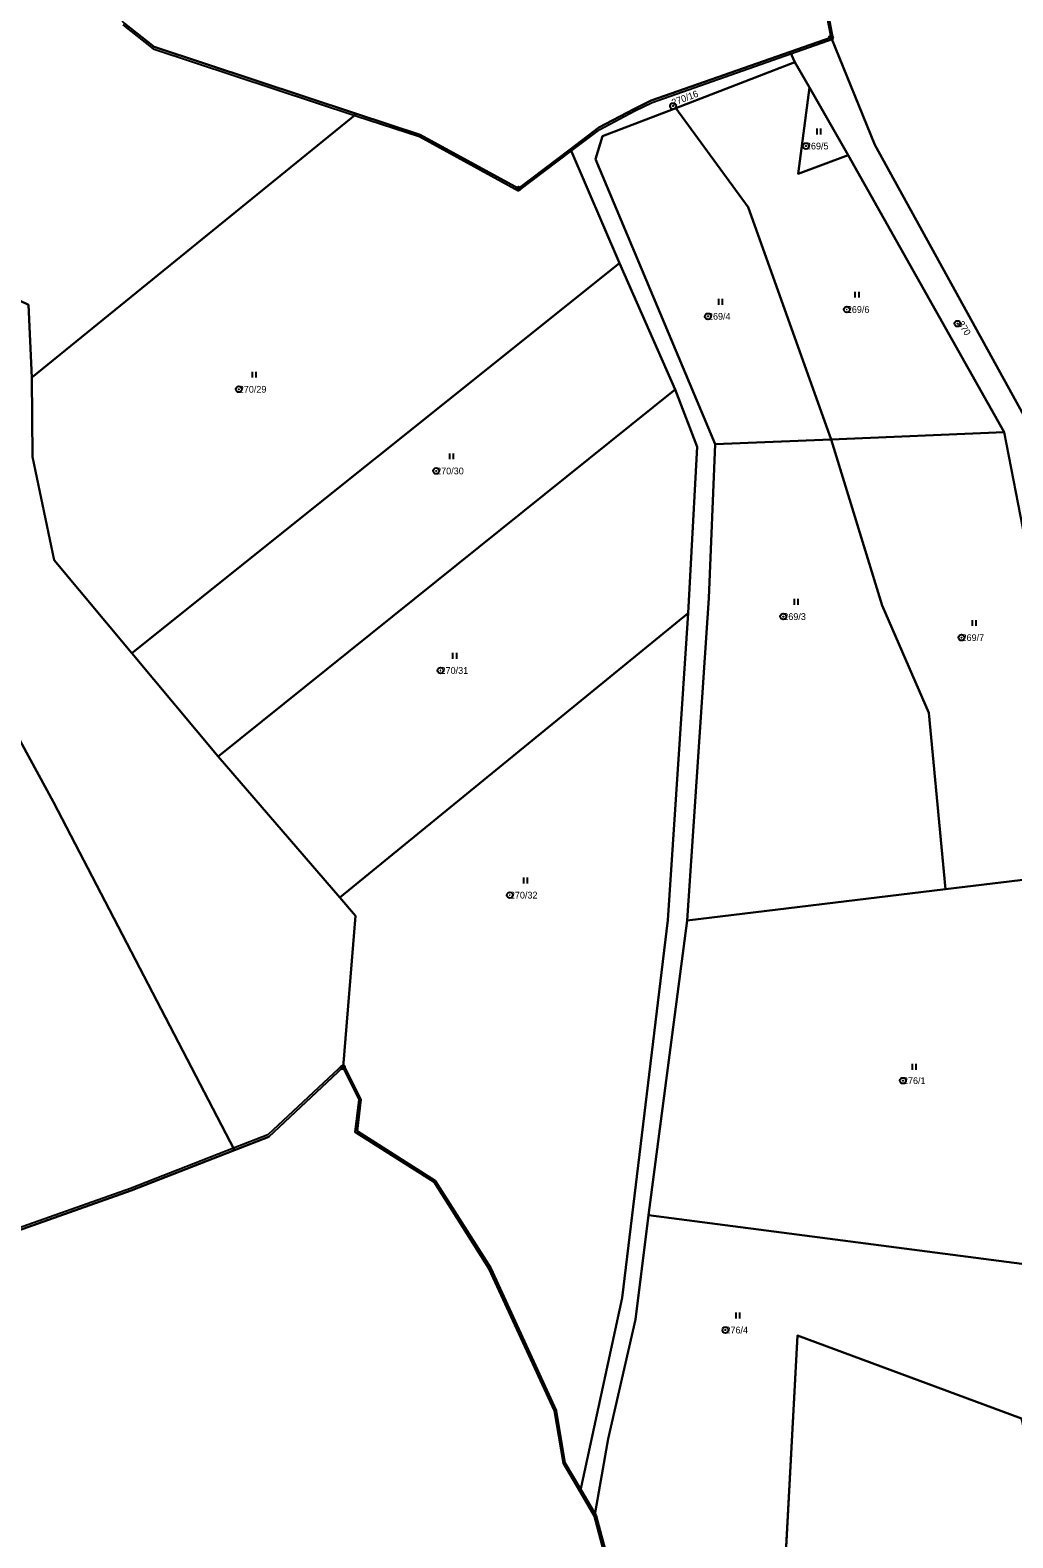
# Model space of a CAD drawing. Extents: x -652854 to -650068, y -1097661 to -1095417.
# Drawn here: x -651941.1 to -651693.7, y -1096486.9 to -1096107.3 of the extents above; entities that cross this region are included whole.
import ezdxf

# ---------------------------------------------------------------- set-up
doc = ezdxf.new("R2010")
doc.units = 0
for name, color, linetype in [('Definiční body parcel', 7, 'Continuous'), ('Geodetické body', 7, 'Continuous'), ('Hranice obcí', 7, 'Continuous'), ('Hranice parcel', 7, 'Continuous'), ('Obvody jako plochy', 7, 'Continuous'), ('Ostatní hranice', 7, 'Continuous'), ('Parcelní čísla', 7, 'Continuous'), ('Značky kultur', 7, 'Continuous')]:
    doc.layers.add(name, color=color, linetype=linetype)

msp = doc.modelspace()

# ---------------------------------------------------------------- linework, layer by layer
at = {"layer": 'Definiční body parcel'}
for centre, radius in [((-651779.27, -1096126.4), 0.75), ((-651779.27, -1096126.4), 0.0327), ((-651745.82, -1096136.48), 0.75), ((-651745.82, -1096136.48), 0.0327), ((-651735.52, -1096177.63), 0.75), ((-651735.52, -1096177.63), 0.0327), ((-651770.48, -1096179.35), 0.75), ((-651770.48, -1096179.35), 0.0327), ((-651707.67, -1096181.19), 0.75), ((-651707.67, -1096181.19), 0.0327), ((-651888.61, -1096197.71), 0.75), ((-651888.61, -1096197.71), 0.0327), ((-651838.92, -1096218.27), 0.75), ((-651838.92, -1096218.27), 0.0327), ((-651751.52, -1096254.93), 0.75), ((-651751.52, -1096254.93), 0.0327), ((-651706.64, -1096260.23), 0.75), ((-651706.64, -1096260.23), 0.0327), ((-651837.81, -1096268.5), 0.75), ((-651837.81, -1096268.5), 0.0327), ((-651820.36, -1096325.06), 0.75), ((-651820.36, -1096325.06), 0.0327), ((-651721.39, -1096371.76), 0.75), ((-651721.39, -1096371.76), 0.0327), ((-651766.09, -1096434.55), 0.75), ((-651766.09, -1096434.55), 0.0327)]:
    msp.add_circle(centre, radius, dxfattribs=at)
at = {"layer": 'Geodetické body'}
for centre, radius in [((-651739.5, -1096109.16), 0.5), ((-651739.5, -1096109.16), 0.001), ((-651818.2, -1096147.2), 0.5), ((-651818.2, -1096147.2), 0.001), ((-651862.37, -1096368.4), 0.5), ((-651862.37, -1096368.4), 0.001)]:
    msp.add_circle(centre, radius, dxfattribs=at)
at = {"layer": 'Hranice obcí'}
for p, q in [((-651739.5, -1096109.16), (-651742.82, -1096091.89)), ((-651917.43, -1096105.58), (-651909.94, -1096111.5)), ((-651749.8, -1096112.77), (-651739.5, -1096109.16)), ((-651909.94, -1096111.5), (-651858.99, -1096128.33)), ((-651784.76, -1096125.05), (-651749.8, -1096112.77)), ((-651797.93, -1096131.83), (-651789.11, -1096127.15)), ((-651789.11, -1096127.15), (-651784.76, -1096125.05)), ((-651858.99, -1096128.33), (-651842.91, -1096133.65)), ((-651805.08, -1096137.25), (-651797.93, -1096131.83)), ((-651842.91, -1096133.65), (-651818.2, -1096147.2)), ((-651818.2, -1096147.2), (-651805.08, -1096137.25)), ((-651862.37, -1096368.4), (-651881.07, -1096385.89)), ((-651858.32, -1096376.5), (-651862.37, -1096368.4)), ((-651859.3, -1096384.74), (-651858.32, -1096376.5)), ((-651881.07, -1096385.89), (-651889.71, -1096389.26)), ((-651839.42, -1096397.34), (-651859.3, -1096384.74)), ((-651889.71, -1096389.26), (-651915.68, -1096399.4)), ((-651825.54, -1096419.18), (-651839.42, -1096397.34)), ((-651915.68, -1096399.4), (-651946.95, -1096410.49)), ((-651809.11, -1096454.91), (-651825.54, -1096419.18)), ((-651806.86, -1096468.18), (-651809.11, -1096454.91)), ((-651802.68, -1096475.27), (-651806.86, -1096468.18)), ((-651799.02, -1096481.47), (-651802.68, -1096475.27)), ((-651796.23, -1096492.24), (-651799.02, -1096481.47))]:
    msp.add_line(p, q, dxfattribs=at)
at = {"layer": 'Hranice parcel'}
for p, q in [((-651728.47, -1096136.15), (-651739.5, -1096109.16)), ((-651748.58, -1096115.33), (-651749.8, -1096112.77)), ((-651778.56, -1096126.98), (-651748.58, -1096115.33)), ((-651748.58, -1096115.33), (-651744.91, -1096121.76)), ((-651744.91, -1096121.76), (-651747.77, -1096143.45)), ((-651744.91, -1096121.76), (-651735.18, -1096138.78)), ((-651797.04, -1096133.95), (-651778.56, -1096126.98)), ((-651778.56, -1096126.98), (-651760.32, -1096151.88)), ((-651940.73, -1096194.74), (-651858.99, -1096128.33)), ((-651798.77, -1096139.74), (-651797.04, -1096133.95)), ((-651792.74, -1096166), (-651805.08, -1096137.25)), ((-651747.77, -1096143.45), (-651735.18, -1096138.78)), ((-651735.18, -1096138.78), (-651695.89, -1096208.49)), ((-651690.95, -1096204.28), (-651728.47, -1096136.15)), ((-651768.64, -1096211.53), (-651798.77, -1096139.74)), ((-651760.32, -1096151.88), (-651739.47, -1096210.32)), ((-651915.5, -1096264.18), (-651792.74, -1096166)), ((-651778.72, -1096197.75), (-651792.74, -1096166)), ((-651941.55, -1096176.41), (-651940.73, -1096194.74)), ((-651940.73, -1096194.74), (-651940.57, -1096214.69)), ((-651893.8, -1096290.17), (-651778.72, -1096197.75)), ((-651773.16, -1096212.17), (-651778.72, -1096197.75)), ((-651988.88, -1096203.13), (-651935.29, -1096301.66)), ((-651768.64, -1096211.53), (-651770.25, -1096250.33)), ((-651739.47, -1096210.32), (-651768.64, -1096211.53)), ((-651695.89, -1096208.49), (-651739.47, -1096210.32)), ((-651739.47, -1096210.32), (-651726.66, -1096252.14)), ((-651695.89, -1096208.49), (-651687.67, -1096250.83)), ((-651940.57, -1096214.69), (-651935.12, -1096240.7)), ((-651775.43, -1096254.03), (-651773.16, -1096212.17)), ((-651935.12, -1096240.7), (-651915.5, -1096264.18)), ((-651770.25, -1096250.33), (-651775.7, -1096331.44)), ((-651726.66, -1096252.14), (-651714.88, -1096279.19)), ((-651775.43, -1096254.03), (-651863.16, -1096325.62)), ((-651780.6, -1096331.34), (-651775.43, -1096254.03)), ((-651915.5, -1096264.18), (-651893.8, -1096290.17)), ((-651714.88, -1096279.19), (-651710.67, -1096323.58)), ((-651863.16, -1096325.62), (-651893.8, -1096290.17)), ((-651935.29, -1096301.66), (-651889.71, -1096389.26)), ((-651673.04, -1096319.05), (-651710.67, -1096323.58)), ((-651863.16, -1096325.62), (-651859.22, -1096330.24)), ((-651775.7, -1096331.44), (-651710.67, -1096323.58)), ((-651859.22, -1096330.24), (-651862.37, -1096368.4)), ((-651792.11, -1096426.4), (-651780.6, -1096331.34)), ((-651785.42, -1096405.64), (-651775.7, -1096331.44)), ((-651788.76, -1096431.88), (-651785.42, -1096405.64)), ((-651685.67, -1096418.62), (-651785.42, -1096405.64)), ((-651802.68, -1096475.27), (-651792.11, -1096426.4)), ((-651795.6, -1096461.91), (-651788.76, -1096431.88)), ((-651747.93, -1096435.93), (-651753.12, -1096532.75)), ((-651691.55, -1096456.85), (-651747.93, -1096435.93)), ((-651799.02, -1096481.47), (-651795.6, -1096461.91))]:
    msp.add_line(p, q, dxfattribs=at)
at = {"layer": 'Obvody jako plochy'}
for points in [[(-651553.76, -1096093.05), (-651577.07, -1096086.78), (-651601.75, -1096075.97), (-651649.43, -1096071.53), (-651700.81, -1096041.54), (-651701.19, -1096046.05), (-651707.42, -1096048.55), (-651714.68, -1096051.04), (-651726.63, -1096058.67), (-651740.88, -1096077.97), (-651742.82, -1096091.89), (-651739.5, -1096109.16), (-651728.47, -1096136.15), (-651690.95, -1096204.28), (-651683.01, -1096251.95), (-651672.67, -1096287.69), (-651664.09, -1096349.66), (-651661.63, -1096368.34), (-651651.15, -1096359.41), (-651600.66, -1096402.57), (-651555.25, -1096501.03)], [(-651636.3, -1096567.46), (-651650.01, -1096473.52), (-651659.4, -1096410.34), (-651663.46, -1096380.62), (-651664.09, -1096349.66), (-651672.67, -1096287.69), (-651683.01, -1096251.95), (-651690.95, -1096204.28), (-651728.47, -1096136.15), (-651739.5, -1096109.16), (-651749.8, -1096112.77), (-651748.58, -1096115.33), (-651744.91, -1096121.76), (-651735.18, -1096138.78), (-651695.89, -1096208.49), (-651687.67, -1096250.83), (-651673.04, -1096319.05), (-651669.61, -1096344.23), (-651667.53, -1096383.22), (-651659.12, -1096440.24), (-651654.35, -1096474.04), (-651642.8, -1096556.06)]]:
    msp.add_lwpolyline(points, dxfattribs=at)
for points in [[(-651943.06, -1096076), (-652047.62, -1096116.05), (-652028.17, -1096124.39), (-652010.08, -1096146.47), (-651982.15, -1096156.91), (-651941.55, -1096176.41), (-651940.73, -1096194.74), (-651858.99, -1096128.33), (-651909.94, -1096111.5), (-651917.43, -1096105.58), (-651942.4, -1096077.39)], [(-651798.77, -1096139.74), (-651797.04, -1096133.95), (-651778.56, -1096126.98), (-651748.58, -1096115.33), (-651749.8, -1096112.77), (-651784.76, -1096125.05), (-651789.11, -1096127.15), (-651797.93, -1096131.83), (-651805.08, -1096137.25), (-651792.74, -1096166), (-651778.72, -1096197.75), (-651773.16, -1096212.17), (-651775.43, -1096254.03), (-651780.6, -1096331.34), (-651792.11, -1096426.4), (-651802.68, -1096475.27), (-651799.02, -1096481.47), (-651795.6, -1096461.91), (-651788.76, -1096431.88), (-651785.42, -1096405.64), (-651775.7, -1096331.44), (-651770.25, -1096250.33), (-651768.64, -1096211.53)], [(-652047.62, -1096116.05), (-652057.53, -1096119.89), (-651988.88, -1096203.13), (-651935.29, -1096301.66), (-651889.71, -1096389.26), (-651881.07, -1096385.89), (-651862.37, -1096368.4), (-651859.22, -1096330.24), (-651863.16, -1096325.62), (-651893.8, -1096290.17), (-651915.5, -1096264.18), (-651935.12, -1096240.7), (-651940.57, -1096214.69), (-651940.73, -1096194.74), (-651941.55, -1096176.41), (-651982.15, -1096156.91), (-652010.08, -1096146.47), (-652028.17, -1096124.39)], [(-651778.56, -1096126.98), (-651760.32, -1096151.88), (-651739.47, -1096210.32), (-651695.89, -1096208.49), (-651735.18, -1096138.78), (-651747.77, -1096143.45), (-651744.91, -1096121.76), (-651748.58, -1096115.33)], [(-652057.53, -1096119.89), (-652066.96, -1096123.51), (-652022.53, -1096233.18), (-652036.99, -1096246.19), (-651992.07, -1096427.63), (-651981.51, -1096423.32), (-651963.26, -1096417), (-651946.95, -1096410.49), (-651915.68, -1096399.4), (-651889.71, -1096389.26), (-651935.29, -1096301.66), (-651988.88, -1096203.13)], [(-651744.91, -1096121.76), (-651747.77, -1096143.45), (-651735.18, -1096138.78)], [(-651798.77, -1096139.74), (-651768.64, -1096211.53), (-651739.47, -1096210.32), (-651760.32, -1096151.88), (-651778.56, -1096126.98), (-651797.04, -1096133.95)], [(-651858.99, -1096128.33), (-651940.73, -1096194.74), (-651940.57, -1096214.69), (-651935.12, -1096240.7), (-651915.5, -1096264.18), (-651792.74, -1096166), (-651805.08, -1096137.25), (-651818.2, -1096147.2), (-651842.91, -1096133.65)], [(-651778.72, -1096197.75), (-651792.74, -1096166), (-651915.5, -1096264.18), (-651893.8, -1096290.17)], [(-651775.43, -1096254.03), (-651773.16, -1096212.17), (-651778.72, -1096197.75), (-651893.8, -1096290.17), (-651863.16, -1096325.62)], [(-651768.64, -1096211.53), (-651770.25, -1096250.33), (-651775.7, -1096331.44), (-651710.67, -1096323.58), (-651714.88, -1096279.19), (-651726.66, -1096252.14), (-651739.47, -1096210.32)], [(-651673.04, -1096319.05), (-651687.67, -1096250.83), (-651695.89, -1096208.49), (-651739.47, -1096210.32), (-651726.66, -1096252.14), (-651714.88, -1096279.19), (-651710.67, -1096323.58)], [(-651792.11, -1096426.4), (-651780.6, -1096331.34), (-651775.43, -1096254.03), (-651863.16, -1096325.62), (-651859.22, -1096330.24), (-651862.37, -1096368.4), (-651858.32, -1096376.5), (-651859.3, -1096384.74), (-651839.42, -1096397.34), (-651825.54, -1096419.18), (-651809.11, -1096454.91), (-651806.86, -1096468.18), (-651802.68, -1096475.27)], [(-651659.51, -1096555.13), (-651646.41, -1096555.8), (-651642.8, -1096556.06), (-651654.35, -1096474.04), (-651659.12, -1096440.24), (-651667.53, -1096383.22), (-651669.61, -1096344.23), (-651673.04, -1096319.05), (-651710.67, -1096323.58), (-651775.7, -1096331.44), (-651785.42, -1096405.64), (-651685.67, -1096418.62), (-651663.59, -1096512.32)], [(-651659.51, -1096555.13), (-651663.59, -1096512.32), (-651685.67, -1096418.62), (-651785.42, -1096405.64), (-651788.76, -1096431.88), (-651795.6, -1096461.91), (-651799.02, -1096481.47), (-651796.23, -1096492.24), (-651783.44, -1096503.05), (-651773.01, -1096517.88), (-651753.12, -1096532.75), (-651747.93, -1096435.93), (-651691.55, -1096456.85), (-651666.79, -1096561.93)], [(-651753.12, -1096532.75), (-651718.02, -1096559.55), (-651698.58, -1096568.61), (-651684.26, -1096565.06), (-651675.59, -1096560.88), (-651666.79, -1096561.93), (-651691.55, -1096456.85), (-651747.93, -1096435.93)]]:
    msp.add_lwpolyline(points, close=True, dxfattribs=at)
at = {"layer": 'Ostatní hranice'}
for p, q in [((-651738.94, -1096109.47), (-651742.32, -1096091.88)), ((-651917.8, -1096105.94), (-651910.14, -1096111.97)), ((-651910.14, -1096111.97), (-651859.11, -1096128.83)), ((-651784.57, -1096125.52), (-651738.94, -1096109.47)), ((-651797.71, -1096132.28), (-651788.93, -1096127.63)), ((-651788.93, -1096127.63), (-651784.57, -1096125.52)), ((-651859.11, -1096128.83), (-651843.12, -1096134.11)), ((-651843.12, -1096134.11), (-651818.17, -1096147.79)), ((-651804.75, -1096137.63), (-651797.71, -1096132.28)), ((-651818.17, -1096147.79), (-651804.75, -1096137.63)), ((-651862.23, -1096367.59), (-651881.26, -1096385.42)), ((-651857.82, -1096376.48), (-651862.23, -1096367.59)), ((-651858.76, -1096384.48), (-651857.82, -1096376.48)), ((-651881.26, -1096385.42), (-651889.9, -1096388.79)), ((-651839.05, -1096397), (-651858.76, -1096384.48)), ((-651889.9, -1096388.79), (-651915.84, -1096398.91)), ((-651825.08, -1096418.97), (-651839.05, -1096397)), ((-651915.84, -1096398.91), (-651947.15, -1096410.02)), ((-651808.63, -1096454.77), (-651825.08, -1096418.97)), ((-651806.4, -1096467.98), (-651808.63, -1096454.77)), ((-651802.26, -1096474.99), (-651806.4, -1096467.98)), ((-651798.54, -1096481.31), (-651802.26, -1096474.99)), ((-651795.65, -1096492.32), (-651798.54, -1096481.31))]:
    msp.add_line(p, q, dxfattribs=at)
at = {"layer": 'Značky kultur'}
for p, q in [((-651743.107, -1096132.045), (-651743.107, -1096133.545)), ((-651742.085, -1096133.545), (-651742.085, -1096132.045)), ((-651733.467, -1096173.145), (-651733.467, -1096174.645)), ((-651732.445, -1096174.645), (-651732.445, -1096173.145)), ((-651767.807, -1096174.915), (-651767.807, -1096176.415)), ((-651766.785, -1096176.415), (-651766.785, -1096174.915)), ((-651885.277, -1096193.275), (-651885.277, -1096194.775)), ((-651884.255, -1096194.775), (-651884.255, -1096193.275)), ((-651835.547, -1096213.835), (-651835.547, -1096215.335)), ((-651834.525, -1096215.335), (-651834.525, -1096213.835)), ((-651748.757, -1096250.495), (-651748.757, -1096251.995)), ((-651747.735, -1096251.995), (-651747.735, -1096250.495)), ((-651703.997, -1096255.795), (-651703.997, -1096257.295)), ((-651702.975, -1096257.295), (-651702.975, -1096255.795)), ((-651834.767, -1096264.065), (-651834.767, -1096265.565)), ((-651833.745, -1096265.565), (-651833.745, -1096264.065)), ((-651816.937, -1096320.625), (-651816.937, -1096322.125)), ((-651815.915, -1096322.125), (-651815.915, -1096320.625)), ((-651719.097, -1096367.545), (-651719.097, -1096369.045)), ((-651718.075, -1096369.045), (-651718.075, -1096367.545)), ((-651763.447, -1096430.115), (-651763.447, -1096431.615)), ((-651762.425, -1096431.615), (-651762.425, -1096430.115))]:
    msp.add_line(p, q, dxfattribs=at)

# ---------------------------------------------------------------- texts
at = {"layer": 'Parcelní čísla'}
for s, rotation, p in [('270/16', 20.385, (-651779.27, -1096126.4)), ('370', 302.661, (-651707.67, -1096181.19))]:
    msp.add_text(s, height=1.7, rotation=rotation, dxfattribs=at).set_placement(p)
for s, p in [('269/5', (-651745.82, -1096137.33)), ('269/6', (-651735.52, -1096178.48)), ('269/4', (-651770.48, -1096180.2)), ('270/29', (-651888.61, -1096198.56)), ('270/30', (-651838.92, -1096219.12)), ('269/3', (-651751.52, -1096255.78)), ('269/7', (-651706.64, -1096261.08)), ('270/31', (-651837.81, -1096269.35)), ('270/32', (-651820.36, -1096325.91)), ('276/1', (-651721.39, -1096372.61)), ('276/4', (-651766.09, -1096435.4))]:
    msp.add_text(s, height=1.7, dxfattribs=at).set_placement(p)

doc.saveas('drawing.dxf')
